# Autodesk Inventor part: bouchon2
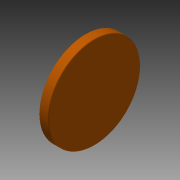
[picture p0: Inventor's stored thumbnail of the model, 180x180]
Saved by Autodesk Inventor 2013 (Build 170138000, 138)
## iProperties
Created: 2012-12
Part Number: bouchon2
Material: Générique
Document SubType Name: Modeling
Designer: jost thierry
Density: 1 g/cm^3
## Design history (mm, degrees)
node "bouchon21"
node "bouchon2"
node "Base1"
